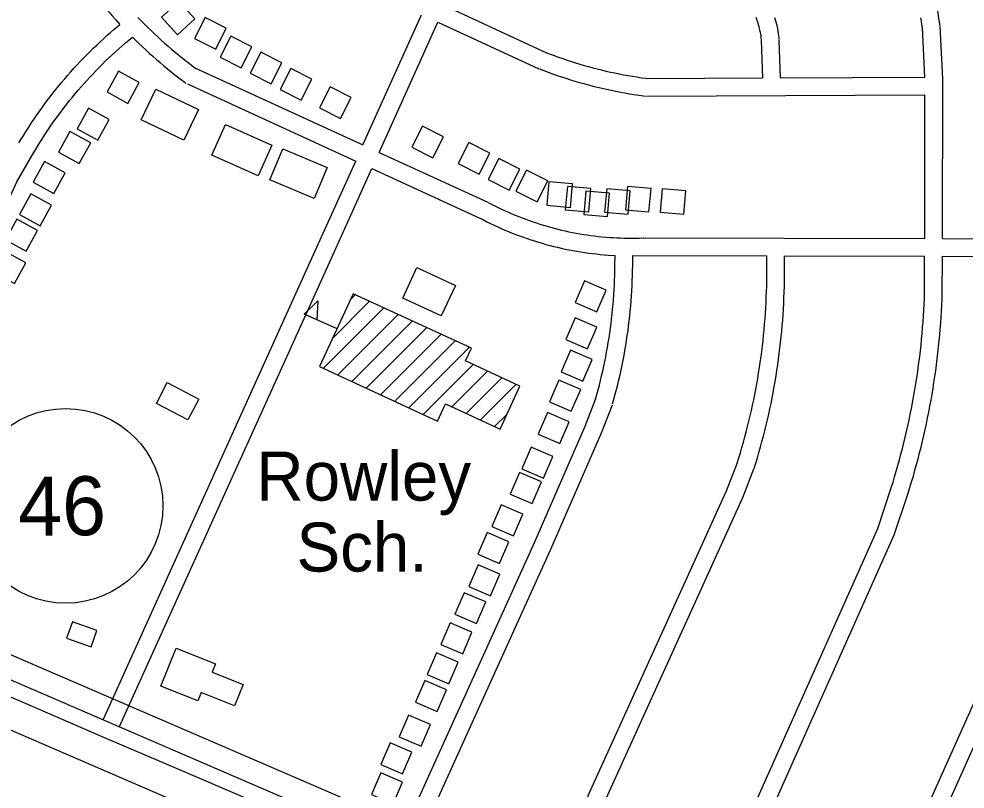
# Model space of a CAD drawing. Extents: x 3704301 to 3742427, y 506229 to 532009.
# Drawn here: x 3709339 to 3710942, y 527098 to 528404 of the extents above; entities that cross this region are included whole.
import ezdxf

# ---------------------------------------------------------------- set-up
doc = ezdxf.new("R2010")
doc.units = 0
for name, color, linetype in [('V-BLDG-IDEN', 7, 'Continuous'), ('V-BLDG-OTLN', 7, 'Continuous'), ('V-RAIL-TRAK', 7, 'Continuous'), ('V-ROAD-CNTR', 7, 'Continuous'), ('V-ROAD-IDEN', 7, 'Continuous'), ('V-TOPO-SHOR', 7, 'Continuous')]:
    doc.layers.add(name, color=color, linetype=linetype)

msp = doc.modelspace()

# ---------------------------------------------------------------- linework, layer by layer
at = {"layer": 'V-BLDG-OTLN'}
for p, q in [((3709900.1, 527927.7), (3709908.6, 527936.2)), ((3709869.9, 527862.2), (3709932.8, 527925)), ((3709854.3, 527811.2), (3709957, 527913.9)), ((3709876.9, 527878.6), (3709822.1, 527903)), ((3709878.5, 527800), (3709981.2, 527902.7)), ((3709902.7, 527788.9), (3710005.4, 527891.6)), ((3709926.9, 527777.7), (3710029.6, 527880.4)), ((3709951.1, 527766.6), (3710053.8, 527869.3)), ((3709975.3, 527755.4), (3710078, 527858.1)), ((3709999.5, 527744.3), (3710102.2, 527847)), ((3710023.7, 527733.1), (3710108.4, 527817.8)), ((3710072.1, 527746.2), (3710132.6, 527806.6)), ((3710096.3, 527735), (3710156.8, 527795.5)), ((3710120.5, 527723.9), (3710181, 527784.3)), ((3710144.7, 527712.7), (3710165.3, 527733.3))]:
    msp.add_line(p, q, dxfattribs=at)
for points in [[(3709580.5, 528406.5), (3709607.4, 528376.9), (3709637, 528403.9), (3709610.1, 528433.4)], [(3709636.4, 528370.2), (3709672.1, 528352.1), (3709690.1, 528387.8), (3709654.5, 528405.9)], [(3709679.5, 528338.9), (3709715.2, 528320.8), (3709733.2, 528356.5), (3709697.6, 528374.5)], [(3709730.4, 528311.4), (3709766.1, 528293.4), (3709784.2, 528329), (3709748.5, 528347.1)], [(3709507.6, 528314.9), (3709488.3, 528279.8), (3709523.3, 528260.5), (3709542.6, 528295.6)], [(3709781.3, 528284), (3709817, 528265.9), (3709835.1, 528301.6), (3709799.4, 528319.7)], [(3709618.3, 528198.3), (3709545.8, 528232.8), (3709570.6, 528284.8), (3709643.1, 528250.3)], [(3709847.9, 528252.7), (3709883.6, 528234.6), (3709901.7, 528270.3), (3709866, 528288.4)], [(3709456.6, 528252.2), (3709437.4, 528217.2), (3709472.4, 528197.9), (3709491.7, 528232.9)], [(3709744.1, 528137.7), (3709665.5, 528172.8), (3709688.6, 528224.7), (3709767.3, 528189.6)], [(3709425.3, 528213), (3709406, 528178), (3709441.1, 528158.7), (3709460.4, 528193.8)], [(3710004.6, 528186.1), (3710040.2, 528168), (3710058.3, 528203.7), (3710022.6, 528221.8)], [(3710082.9, 528158.7), (3710118.6, 528140.6), (3710136.7, 528176.3), (3710101, 528194.4)], [(3709838.9, 528099.5), (3709763.9, 528131.1), (3709785.9, 528183.2), (3709860.9, 528151.6)], [(3709382.2, 528162.1), (3709363, 528127.1), (3709398, 528107.8), (3709417.3, 528142.8)], [(3710133.8, 528131.3), (3710169.5, 528113.2), (3710187.6, 528148.9), (3710151.9, 528166.9)], [(3710180.8, 528111.7), (3710216.5, 528093.6), (3710234.6, 528129.3), (3710198.9, 528147.4)], [(3710233.1, 528087.7), (3710272.9, 528084.2), (3710276.4, 528124.1), (3710236.5, 528127.5)], [(3710264.4, 528079.8), (3710304.3, 528076.4), (3710307.7, 528116.2), (3710267.9, 528119.7)], [(3710331, 528075.9), (3710370.9, 528072.5), (3710374.3, 528112.3), (3710334.5, 528115.8)], [(3710366.3, 528079.8), (3710406.1, 528076.4), (3710409.6, 528116.2), (3710369.7, 528119.7)], [(3710425, 528075.9), (3710464.9, 528072.5), (3710468.3, 528112.3), (3710428.5, 528115.8)], [(3709358.7, 528107.3), (3709339.5, 528072.2), (3709374.5, 528053), (3709393.8, 528088)], [(3710295.8, 528072), (3710335.6, 528068.6), (3710339.1, 528108.4), (3710299.2, 528111.9)], [(3709335.2, 528064.2), (3709316, 528029.2), (3709351, 528009.9), (3709370.3, 528044.9)], [(3709315.6, 528009.4), (3709296.4, 527974.3), (3709331.4, 527955), (3709350.7, 527990.1)], [(3710013.1, 527982.1), (3710078.1, 527951.9), (3710054.1, 527900.1), (3709989, 527930.3)], [(3710317.6, 527907.3), (3710333.4, 527944.1), (3710296.7, 527959.9), (3710280.9, 527923.1)], [(3709847.8, 527814.2), (3710047.9, 527722), (3710061.3, 527751.1), (3710153.9, 527708.5), (3710187.4, 527781.4), (3710095.3, 527823.8), (3710105.3, 527845.5), (3709904.8, 527937.9)], [(3709822.1, 527903), (3709844.9, 527925.7), (3709843.2, 527893.6)], [(3710302, 527844.6), (3710317.8, 527881.4), (3710281, 527897.2), (3710265.2, 527860.5)], [(3710294.1, 527789.8), (3710309.9, 527826.6), (3710273.2, 527842.4), (3710257.4, 527805.6)], [(3709643.4, 527759.3), (3709625, 527724.1), (3709571.6, 527751.9), (3709590, 527787.1)], [(3710274.5, 527738.9), (3710290.4, 527775.6), (3710253.6, 527791.5), (3710237.8, 527754.7)], [(3710255, 527684.1), (3710270.8, 527720.8), (3710234, 527736.6), (3710218.2, 527699.9)], [(3710227.5, 527625.3), (3710243.4, 527662), (3710206.6, 527677.9), (3710190.8, 527641.1)], [(3710208, 527582.2), (3710223.8, 527619), (3710187, 527634.8), (3710171.2, 527598)], [(3710176.6, 527527.4), (3710192.4, 527564.1), (3710155.7, 527580), (3710139.9, 527543.2)], [(3710153.1, 527480.4), (3710168.9, 527517.1), (3710132.2, 527532.9), (3710116.4, 527496.2)], [(3710137.5, 527425.6), (3710153.3, 527462.3), (3710116.5, 527478.1), (3710100.7, 527441.4)], [(3710114, 527378.6), (3710129.8, 527415.3), (3710093, 527431.1), (3710077.2, 527394.4)], [(3709461.2, 527339.4), (3709471, 527367), (3709429.3, 527381.7), (3709419.5, 527354)], [(3710090.5, 527327.6), (3710106.3, 527364.4), (3710069.5, 527380.2), (3710053.7, 527343.5)], [(3709579.4, 527272.5), (3709605.4, 527337.3), (3709671.7, 527310.7), (3709666, 527296.3), (3709718.5, 527275.3), (3709704.1, 527239.3), (3709647.6, 527261.9), (3709641.9, 527247.5)], [(3710067, 527276.7), (3710082.8, 527313.5), (3710046, 527329.3), (3710030.2, 527292.5)], [(3710047.4, 527229.7), (3710063.2, 527266.5), (3710026.5, 527282.3), (3710010.6, 527245.5)], [(3710020, 527171), (3710035.8, 527207.7), (3709999, 527223.5), (3709983.2, 527186.8)], [(3709988.6, 527124), (3710004.4, 527160.7), (3709967.7, 527176.5), (3709951.9, 527139.8)], [(3709973, 527073.1), (3709988.8, 527109.8), (3709952, 527125.6), (3709936.2, 527088.9)]]:
    msp.add_lwpolyline(points, close=True, dxfattribs=at)
at = {"layer": 'V-RAIL-TRAK'}
msp.add_lwpolyline([(3708568.6, 527526.1), (3708881.1, 527391.4), (3708954, 527358.6), (3709233.5, 527237.8), (3709568.2, 527093), (3709758.4, 527010.6), (3709933.2, 526934.3)], dxfattribs=at)
at = {"layer": 'V-ROAD-CNTR'}
for points in [[(3710899.2, 528392), (3710898.3, 528398.2), (3710897.4, 528404.4), (3710896.4, 528410.7), (3710895.3, 528416.9), (3710894.1, 528423.1), (3710892.8, 528429.3), (3710891.5, 528435.5), (3710890, 528441.7), (3710888.5, 528447.8), (3710887, 528453.9), (3710885.3, 528460.1), (3710883.6, 528466.1), (3710881.7, 528472.2), (3710879.8, 528478.2), (3710877.8, 528484.3), (3710875.8, 528490.2), (3710873.7, 528496.2), (3710871.4, 528502.1), (3710869.2, 528508), (3710866.8, 528513.9), (3710865, 528518.2)], [(3709475.9, 528433.6), (3709481, 528427.4), (3709486.2, 528421.2), (3709491.5, 528415.1), (3709496.9, 528409), (3709502.3, 528402.9), (3709510, 528394.4)], [(3710060.6, 528425.5), (3710232.3, 528346.4)], [(3709540.5, 528405.9), (3709546, 528400.3), (3709551.5, 528394.7), (3709557, 528389.3), (3709562.6, 528383.8), (3709568.3, 528378.4), (3709574, 528373.1), (3709579.8, 528367.8), (3709585.6, 528362.6), (3709591.5, 528357.5), (3709597.4, 528352.4), (3709603.4, 528347.4), (3709609.4, 528342.4), (3709615.5, 528337.5), (3709621.6, 528332.6), (3709627.8, 528327.8), (3709634, 528323.1), (3709639.6, 528318.9)], [(3709921.6, 528189.9), (3710021, 528410.7)], [(3710587.1, 528406.3), (3710588.3, 528403.3), (3710589.3, 528400.2), (3710590.3, 528397.1), (3710591.3, 528393.9), (3710592.1, 528390.8), (3710592.9, 528387.6), (3710593.6, 528384.4), (3710594.3, 528381.2), (3710594.9, 528378), (3710595.4, 528374.8), (3710595.8, 528371.5), (3710596.2, 528368.3), (3710596.4, 528365.9)], [(3710619, 528405.9), (3710620.1, 528402.2), (3710621.2, 528398.4), (3710622.1, 528394.5), (3710623, 528390.7), (3710623.8, 528386.9), (3710624.5, 528383), (3710625.1, 528379.1), (3710625.6, 528375.2), (3710626, 528371.3), (3710626.3, 528368.7)], [(3710869.4, 528387.9), (3710868.6, 528393.9), (3710867.7, 528399.8), (3710866.8, 528405.6)], [(3709338.8, 528193.3), (3709342.8, 528200), (3709346.9, 528206.8), (3709351.1, 528213.5), (3709355.3, 528220.1), (3709359.6, 528226.7), (3709364, 528233.3), (3709368.4, 528239.8), (3709372.9, 528246.2), (3709377.5, 528252.6), (3709382.1, 528259), (3709386.8, 528265.3), (3709391.6, 528271.6), (3709396.4, 528277.8), (3709401.3, 528284), (3709406.2, 528290.1), (3709411.3, 528296.2), (3709416.3, 528302.2), (3709421.5, 528308.2), (3709426.7, 528314.1), (3709432, 528319.9), (3709437.3, 528325.7), (3709442.7, 528331.5), (3709448.1, 528337.2), (3709453.6, 528342.8), (3709459.2, 528348.4), (3709464.8, 528353.9), (3709470.5, 528359.3), (3709476.2, 528364.7), (3709482, 528370.1), (3709487.9, 528375.3), (3709493.8, 528380.6), (3709499.7, 528385.7), (3709510, 528394.4)], [(3709948.8, 528177.4), (3710048.3, 528398.2)], [(3710048.3, 528398.2), (3710219.7, 528319.2)], [(3710873.5, 528304.8), (3710869.3, 528389.2)], [(3710903.2, 528031.2), (3710903.7, 528301.9), (3710899.3, 528390.7)], [(3709364.6, 528178), (3709368.5, 528184.6), (3709372.4, 528191.1), (3709376.4, 528197.5), (3709380.5, 528203.9), (3709384.6, 528210.2), (3709388.8, 528216.5), (3709393.1, 528222.7), (3709397.4, 528229), (3709401.8, 528235.1), (3709406.3, 528241.2), (3709410.8, 528247.3), (3709415.3, 528253.3), (3709420, 528259.3), (3709424.7, 528265.2), (3709429.5, 528271.1), (3709434.3, 528276.9), (3709439.2, 528282.7), (3709444.1, 528288.4), (3709449.1, 528294.1), (3709454.2, 528299.7), (3709459.3, 528305.3), (3709464.5, 528310.8), (3709469.7, 528316.3), (3709475, 528321.7), (3709480.3, 528327.1), (3709485.7, 528332.3), (3709491.2, 528337.6), (3709496.7, 528342.8), (3709502.3, 528347.9), (3709507.9, 528353), (3709513.5, 528358), (3709519.3, 528362.9), (3709525, 528367.8), (3709531, 528372.8)], [(3709531, 528372.8), (3709536, 528367.8), (3709541.8, 528362.2), (3709547.7, 528356.6), (3709553.7, 528351.1), (3709559.7, 528345.6), (3709565.7, 528340.2), (3709571.8, 528334.8), (3709578, 528329.5), (3709584.2, 528324.3), (3709590.4, 528319.1), (3709596.7, 528314.1), (3709603.1, 528309), (3709609.5, 528304), (3709616, 528299.1), (3709621.7, 528294.9)], [(3710596.3, 528366.8), (3710598.2, 528303.6)], [(3710626.3, 528367.7), (3710628.2, 528303.7)], [(3710231.4, 528346.8), (3710238.6, 528344), (3710245.7, 528341.4), (3710252.9, 528338.8), (3710260.1, 528336.3), (3710267.3, 528333.9), (3710274.6, 528331.5), (3710281.8, 528329.2), (3710289.1, 528327), (3710296.4, 528324.9), (3710303.8, 528322.8), (3710311.1, 528320.8), (3710318.5, 528318.9), (3710325.9, 528317.1), (3710333.3, 528315.3), (3710340.8, 528313.6), (3710348.2, 528312), (3710355.7, 528310.5), (3710363.2, 528309.1), (3710370.7, 528307.7), (3710378.2, 528306.4), (3710385.7, 528305.2), (3710393.2, 528304), (3710400.8, 528303), (3710404.1, 528302.5)], [(3709636.9, 528320.5), (3709921.6, 528189.9)], [(3710220.7, 528318.8), (3710228, 528316), (3710235.4, 528313.2), (3710242.9, 528310.5), (3710250.4, 528307.9), (3710257.9, 528305.4), (3710265.4, 528302.9), (3710273, 528300.5), (3710280.6, 528298.2), (3710288.2, 528296), (3710295.8, 528293.9), (3710303.5, 528291.8), (3710311.2, 528289.8), (3710318.9, 528287.9), (3710326.6, 528286.1), (3710334.3, 528284.4), (3710342.1, 528282.7), (3710349.8, 528281.1), (3710357.6, 528279.6), (3710365.4, 528278.2), (3710373.2, 528276.8), (3710381.1, 528275.5), (3710388.9, 528274.4), (3710396.7, 528273.3), (3710400.2, 528272.8)], [(3710628.2, 528303.7), (3710873.5, 528304.8)], [(3709624.4, 528293.3), (3709909.3, 528162.6)], [(3710402.1, 528302.7), (3710598.2, 528303.6)], [(3710402.2, 528272.7), (3710873.7, 528274.8)], [(3710873.2, 528031.2), (3710873.7, 528274.8)], [(3709027.9, 527453.3), (3709335.3, 528127.5), (3709364.7, 528178.1)], [(3709948.8, 528177.4), (3710133.1, 528092.9)], [(3709481.3, 527215.7), (3709838, 528004.5), (3709909.3, 528162.6)], [(3709508.6, 527203.3), (3709865.4, 527992.1), (3709936.5, 528150.1)], [(3709936.5, 528150.1), (3710120.6, 528065.6)], [(3710133.8, 528092.5), (3710139.5, 528089.5), (3710145.2, 528086.7), (3710150.8, 528083.9), (3710156.5, 528081.1), (3710162.3, 528078.5), (3710168.1, 528075.9), (3710173.9, 528073.3), (3710179.7, 528070.9), (3710185.6, 528068.5), (3710191.5, 528066.2), (3710197.4, 528064), (3710203.3, 528061.8), (3710209.3, 528059.7), (3710215.3, 528057.7), (3710221.3, 528055.8), (3710227.4, 528053.9), (3710233.4, 528052.1), (3710239.5, 528050.4), (3710245.6, 528048.8), (3710251.8, 528047.2), (3710257.9, 528045.7), (3710264.1, 528044.3), (3710270.3, 528043), (3710276.5, 528041.7), (3710282.7, 528040.5), (3710288.9, 528039.4), (3710295.2, 528038.4), (3710301.4, 528037.4), (3710307.7, 528036.5), (3710314, 528035.7), (3710320.2, 528035), (3710326.5, 528034.3), (3710332.8, 528033.8), (3710339.2, 528033.3), (3710345.5, 528032.9), (3710351.8, 528032.5), (3710358.1, 528032.3), (3710364.4, 528032.1), (3710370.8, 528032), (3710377.1, 528032), (3710383.4, 528032), (3710389.7, 528032.1), (3710396.1, 528032.3), (3710396.9, 528032.4)], [(3710119.9, 528066), (3710125.7, 528062.9), (3710131.7, 528059.8), (3710137.7, 528056.9), (3710143.8, 528054), (3710149.8, 528051.2), (3710155.9, 528048.4), (3710162.1, 528045.8), (3710168.3, 528043.2), (3710174.5, 528040.6), (3710180.7, 528038.2), (3710187, 528035.8), (3710193.3, 528033.6), (3710199.6, 528031.4), (3710205.9, 528029.2), (3710212.3, 528027.2), (3710218.7, 528025.2), (3710225.1, 528023.3), (3710231.6, 528021.5), (3710238, 528019.7), (3710244.5, 528018.1), (3710251, 528016.5), (3710257.6, 528015), (3710264.1, 528013.6), (3710270.7, 528012.3), (3710277.2, 528011), (3710283.8, 528009.8), (3710290.4, 528008.7), (3710297.1, 528007.7), (3710303.7, 528006.8), (3710310.3, 528005.9), (3710317, 528005.2), (3710323.7, 528004.5), (3710330.3, 528003.9), (3710337, 528003.4), (3710348.6, 528002.6)], [(3710397.6, 528032.4), (3710873.2, 528031.2)], [(3710903.2, 528031.2), (3711016.5, 528030.9), (3711137.9, 528030.7)], [(3710315.6, 527759.2), (3710317.8, 527767.1), (3710320, 527775), (3710322.1, 527782.9), (3710324, 527790.9), (3710325.9, 527798.8), (3710327.8, 527806.8), (3710329.5, 527814.8), (3710331.2, 527822.8), (3710332.8, 527830.8), (3710334.4, 527838.9), (3710335.8, 527846.9), (3710337.2, 527855), (3710338.5, 527863.1), (3710339.7, 527871.1), (3710340.8, 527879.2), (3710341.9, 527887.4), (3710342.9, 527895.5), (3710343.8, 527903.6), (3710344.6, 527911.8), (3710345.4, 527919.9), (3710346, 527928.1), (3710346.6, 527936.2), (3710347.1, 527944.4), (3710347.6, 527952.6), (3710347.9, 527960.7), (3710348.2, 527968.9), (3710348.4, 527977.1), (3710348.5, 527985.3), (3710348.6, 528002.6)], [(3710344.5, 527751), (3710346.8, 527759.1), (3710349, 527767.3), (3710351.1, 527775.5), (3710353.2, 527783.7), (3710355.2, 527792), (3710357.1, 527800.2), (3710358.9, 527808.5), (3710360.6, 527816.8), (3710362.3, 527825.1), (3710363.9, 527833.4), (3710365.4, 527841.7), (3710366.8, 527850.1), (3710368.1, 527858.4), (3710369.4, 527866.8), (3710370.6, 527875.2), (3710371.7, 527883.6), (3710372.7, 527892), (3710373.6, 527900.4), (3710374.5, 527908.9), (3710375.2, 527917.3), (3710375.9, 527925.7), (3710376.5, 527934.2), (3710377.1, 527942.6), (3710377.5, 527951.1), (3710377.9, 527959.6), (3710378.2, 527968), (3710378.4, 527976.5), (3710378.5, 527985), (3710378.6, 528002.4)], [(3710378.6, 528002.4), (3710605.5, 528001.9)], [(3710555.5, 527650.6), (3710558.3, 527659.5), (3710561, 527668.4), (3710563.6, 527677.2), (3710566.1, 527686.1), (3710568.5, 527695), (3710570.9, 527704), (3710573.2, 527712.9), (3710575.4, 527721.9), (3710577.5, 527730.9), (3710579.6, 527739.9), (3710581.6, 527749), (3710583.5, 527758), (3710585.3, 527767.1), (3710587.1, 527776.1), (3710588.7, 527785.2), (3710590.3, 527794.3), (3710591.8, 527803.5), (3710593.3, 527812.6), (3710594.6, 527821.7), (3710595.9, 527830.9), (3710597.1, 527840.1), (3710598.3, 527849.2), (3710599.3, 527858.4), (3710600.3, 527867.6), (3710601.2, 527876.8), (3710602, 527886), (3710602.7, 527895.2), (3710603.4, 527904.5), (3710603.9, 527913.7), (3710604.4, 527922.9), (3710604.9, 527932.2), (3710605.2, 527941.4), (3710605.5, 527950.6), (3710605.6, 527959.9), (3710605.7, 527969.1), (3710605.8, 527978.4), (3710605.7, 527987.6), (3710605.5, 528001.9)], [(3710584.2, 527641.7), (3710587, 527650.7), (3710589.7, 527659.8), (3710592.4, 527668.9), (3710595, 527678.1), (3710597.5, 527687.2), (3710599.9, 527696.4), (3710602.3, 527705.6), (3710604.6, 527714.9), (3710606.8, 527724.1), (3710608.9, 527733.4), (3710610.9, 527742.6), (3710612.9, 527751.9), (3710614.7, 527761.3), (3710616.5, 527770.6), (3710618.3, 527779.9), (3710619.9, 527789.3), (3710621.5, 527798.7), (3710622.9, 527808), (3710624.3, 527817.4), (3710625.7, 527826.9), (3710626.9, 527836.3), (3710628, 527845.7), (3710629.1, 527855.1), (3710630.1, 527864.6), (3710631, 527874), (3710631.9, 527883.5), (3710632.6, 527893), (3710633.3, 527902.5), (3710633.9, 527911.9), (3710634.4, 527921.4), (3710634.8, 527930.9), (3710635.2, 527940.4), (3710635.5, 527949.9), (3710635.6, 527959.4), (3710635.7, 527968.9), (3710635.8, 527978.4), (3710635.7, 527987.9), (3710635.5, 528001.8)], [(3710635.5, 528001.8), (3710873.1, 528001.2)], [(3710873, 527934.6), (3710873.1, 528001.2)], [(3710903, 527934.6), (3710903.1, 528001.2)], [(3710903.1, 528001.2), (3711016.4, 528000.9), (3711136.8, 528000.7)], [(3710816.5, 527608.6), (3710819.5, 527618.2), (3710822.3, 527627.7), (3710825.1, 527637.2), (3710827.8, 527646.7), (3710830.5, 527656.2), (3710833, 527665.8), (3710835.5, 527675.4), (3710837.9, 527685), (3710840.3, 527694.7), (3710842.5, 527704.3), (3710844.7, 527714), (3710846.8, 527723.7), (3710848.8, 527733.4), (3710850.7, 527743.1), (3710852.6, 527752.8), (3710854.4, 527762.6), (3710856.1, 527772.3), (3710857.7, 527782.1), (3710859.3, 527791.9), (3710860.8, 527801.7), (3710862.2, 527811.5), (3710863.5, 527821.3), (3710864.7, 527831.1), (3710865.9, 527841), (3710867, 527850.8), (3710868, 527860.7), (3710868.9, 527870.5), (3710869.7, 527880.4), (3710870.5, 527890.3), (3710871.2, 527900.2), (3710871.8, 527910.1), (3710872.4, 527920), (3710872.8, 527929.9), (3710873, 527935.2)], [(3710845.2, 527599.8), (3710848.2, 527609.4), (3710851.1, 527619.1), (3710854, 527628.8), (3710856.7, 527638.6), (3710859.4, 527648.4), (3710862.1, 527658.2), (3710864.6, 527668), (3710867.1, 527677.9), (3710869.4, 527687.7), (3710871.7, 527697.6), (3710874, 527707.5), (3710876.1, 527717.4), (3710878.2, 527727.4), (3710880.2, 527737.3), (3710882.1, 527747.3), (3710883.9, 527757.3), (3710885.7, 527767.3), (3710887.3, 527777.3), (3710888.9, 527787.3), (3710890.4, 527797.3), (3710891.9, 527807.4), (3710893.2, 527817.4), (3710894.5, 527827.5), (3710895.7, 527837.6), (3710896.8, 527847.7), (3710897.8, 527857.8), (3710898.8, 527867.9), (3710899.6, 527878), (3710900.4, 527888.1), (3710901.1, 527898.2), (3710901.8, 527908.3), (3710902.3, 527918.5), (3710902.8, 527928.6), (3710903, 527934)], [(3709979, 527000.8), (3710212.7, 527517), (3710298.1, 527713.5), (3710316, 527760.5)], [(3710006.3, 526988.4), (3710240.1, 527504.8), (3710325.9, 527702.2), (3710344.1, 527749.7)], [(3710412, 526855.4), (3709792.3, 527123.9), (3708938.2, 527492.3), (3708551.2, 527660.8)], [(3710217, 526898), (3710537.5, 527603.7), (3710555.9, 527651.5)], [(3710244.3, 526885.6), (3710565.2, 527592.2), (3710583.9, 527640.8)], [(3710378.3, 526828.1), (3709806.7, 527074.8), (3709110.3, 527375.7), (3708535.3, 527624.1)], [(3710460.3, 526791.5), (3710793.6, 527539.8), (3710816.6, 527608.9)], [(3710487.7, 526779.3), (3710821.6, 527528.9), (3710845.1, 527599.5)], [(3710861.6, 527032.2), (3711015.7, 527375.8)], [(3710889, 527019.9), (3711043, 527363.5)]]:
    msp.add_lwpolyline(points, dxfattribs=at)
at = {"layer": 'V-ROAD-IDEN'}
msp.add_circle((3709417.8, 527578.2), 165, dxfattribs=at)
at = {"layer": 'V-TOPO-SHOR'}
msp.add_lwpolyline([(3709740.1, 527075.7), (3709585.7, 527141.3), (3709478.6, 527187.5), (3709358.1, 527239.6), (3709233.5, 527293), (3709111.1, 527347.4)], dxfattribs=at)

# ---------------------------------------------------------------- texts
at = {"layer": 'V-BLDG-IDEN'}
for s, p in [('Rowley', (3709740.9, 527587.2)), ('Sch.', (3709809, 527466.9))]:
    msp.add_text(s, height=83, dxfattribs=at).set_placement(p)
at = {"layer": 'V-ROAD-IDEN'}
msp.add_text('46', height=100, rotation=0.4871, dxfattribs=at).set_placement((3709337.9, 527527.5))

doc.saveas('drawing.dxf')
